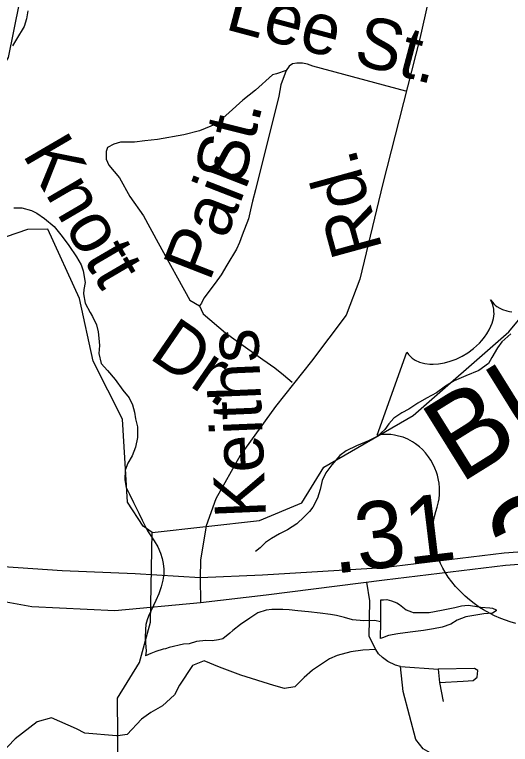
# Model space of a CAD drawing. Extents: x 2001466 to 31450019, y -30647475 to 847247.
# Drawn here: x 2164743 to 2166590, y 747443 to 750161 of the extents above; entities that cross this region are included whole.
import ezdxf

# ---------------------------------------------------------------- set-up
doc = ezdxf.new("R2010")
doc.units = 0
for name, color, linetype in [('Exist Hydrographic Creek Single Shore', 7, 'Continuous'), ('Exist Hydrographic Misc Water Feature', 7, 'Continuous'), ('Exist Road Non-System Type 51', 7, 'Continuous'), ('Exist Road Non-System Type 51 Label', 7, 'Continuous'), ('Exist Road Primary US Divided Attributed', 7, 'Continuous'), ('Exist Road Primary US Mileage Hundredths English Label', 7, 'Continuous'), ('Exist Road Primary US Shield CELL', 7, 'Continuous'), ('Exist Road Primary US Shield Number Label', 7, 'Continuous'), ('Exist Road Secondary Type 51 Attributed', 7, 'Continuous'), ('Exist Road Secondary Type 51 Label', 7, 'Continuous')]:
    doc.layers.add(name, color=color, linetype=linetype)

msp = doc.modelspace()

# ---------------------------------------------------------------- linework, layer by layer
at = {"layer": 'Exist Hydrographic Creek Single Shore'}
for points in [[(2165255.1, 748232.2), (2165222, 748255.9), (2165163.2, 748345.7), (2165145.2, 748654.4), (2165035.2, 748869.9), (2164984.2, 749103.9), (2164866.1, 749362.2), (2164791.2, 749360.4), (2164591.1, 749292.4), (2164549.1, 749335.9), (2164564.2, 749752.2), (2164720.1, 750001.6), (2164761.1, 750204.1), (2164758.2, 750686.4), (2164716.2, 750861.2), (2164615.1, 750994.4), (2164540.2, 751051.7), (2164539.2, 751166.6), (2164580.2, 751218.2), (2164572.2, 751300.4), (2164471.1, 751443.5), (2164568.1, 751933.6), (2164482.2, 752407.8), (2164448.2, 752467.5)], [(2165126.8, 747475), (2165126.1, 747614.9), (2165208.1, 747747.7), (2165249.1, 747897.8), (2165255.1, 748232.2)], [(2165559.1, 745607.9), (2165536.2, 745641.5), (2165510.1, 745907.8), (2165583.1, 746185), (2165583.1, 746309.8), (2165515.1, 746458.7), (2165440.2, 746565.3), (2165380.1, 746865), (2165262.2, 746972.4), (2165127.1, 747414.7), (2165126.8, 747475)]]:
    msp.add_lwpolyline(points, dxfattribs=at)
at = {"layer": 'Exist Hydrographic Misc Water Feature'}
for points in [[(2165255.1, 748232.2), (2165655.1, 748276.5), (2165813.2, 748342.2), (2165895.2, 748475), (2166227.2, 748668.3), (2166584.2, 748979.2), (2166766.1, 749198.6), (2166790.1, 749306.3), (2166906.1, 749540.2), (2167163.1, 749708.7), (2167353.2, 749934.5), (2167469.2, 750210.9), (2167476.2, 750351.9), (2167409.1, 750418.8), (2167392.1, 750501.2), (2167458.1, 750624.5), (2167607.2, 750785.4), (2167681, 750918.5), (2167678.2, 751420.4), (2167708.1, 751961.1), (2167839.1, 752493.1), (2167953.1, 752851.6)], [(2164791.6, 750175.6), (2164787.5, 750145.4), (2164777.7, 750117.6), (2164749.8, 750069.6), (2164734.2, 750045.1)], [(2164739.6, 749441.5), (2164769.3, 749441.9), (2164805.6, 749431.9), (2164825.5, 749422), (2164853.6, 749402), (2164889.9, 749372.5), (2164919.8, 749334.4), (2164944.2, 749300.7), (2164972.7, 749259), (2164990.5, 749229.1), (2164998.7, 749207.2), (2165005.1, 749163.3), (2165001.2, 749137.1), (2164999.4, 749121.1), (2165005.1, 749087), (2165023.6, 749051.4), (2165033.4, 749037.3), (2165048.2, 749005.4), (2165053.9, 748979.4), (2165056.4, 748955.5), (2165058.4, 748929.3), (2165056.4, 748899.5), (2165064.6, 748861.4), (2165088.8, 748835.8), (2165117.1, 748801.9), (2165145.4, 748762), (2165169.6, 748733.9), (2165181.4, 748708.2), (2165189.4, 748680.2), (2165193.5, 748656.1), (2165200.1, 748626.3), (2165200.1, 748586.5), (2165192.5, 748550.4), (2165180.6, 748518.1), (2165164.6, 748490.1), (2165155.2, 748463.9), (2165152.9, 748428.2), (2165158.9, 748400.1), (2165171.2, 748374.3), (2165185.3, 748344.2), (2165205.4, 748304.6), (2165217.7, 748278.4), (2165237.8, 748238.5), (2165262.6, 748200.7), (2165276.4, 748179.1), (2165286.8, 748154.8), (2165292.4, 748134.9), (2165296.7, 748117.2), (2165298.9, 748095), (2165298.7, 748081.2)], [(2166591.2, 748972.1), (2166557.8, 748941.9), (2166542.2, 748919.9), (2166520.4, 748883.8), (2166508.1, 748861.7), (2166472.5, 748835.5), (2166424.5, 748815.2), (2166380.6, 748797), (2166348.8, 748776.7), (2166315, 748752.7), (2166276.8, 748732.5), (2166245.3, 748714.1), (2166211.4, 748692.1), (2166185.2, 748677.8), (2166155.4, 748657.9), (2166137.6, 748637.5), (2166121.6, 748615.5), (2166093.9, 748589.3), (2166061.9, 748573.1), (2166016, 748554.9), (2165978.1, 748536.6), (2165954.3, 748518.7), (2165924.4, 748484.3), (2165902.8, 748454.4), (2165888.9, 748426.4), (2165880.9, 748392.3), (2165871, 748360.2), (2165853.4, 748325.9), (2165841.3, 748309.9), (2165821.4, 748290.2), (2165793.7, 748264), (2165759.9, 748241.5), (2165729.8, 748227.4), (2165700, 748209.2), (2165678.1, 748195), (2165658.2, 748175.3), (2165640.1, 748161)], [(2165298.7, 748081.2), (2165298.9, 748077.1), (2165294.8, 748055), (2165289.3, 748029.1), (2165279.5, 748003), (2165269.4, 747978.9), (2165241.9, 747920.7), (2165236.2, 747906.9), (2165231.9, 747888.9), (2165230.2, 747870.9), (2165228.6, 747840.7), (2165230.5, 747820.9), (2165232.5, 747790.6), (2165230.9, 747772.6)], [(2166107.5, 747899.7), (2166107.1, 747981.7), (2166117.3, 747981.8), (2166129.2, 747982), (2166146.8, 747978.1), (2166167.1, 747970.2), (2166177.4, 747964.2), (2166189.7, 747954.2), (2166201.6, 747944.3), (2166221.5, 747936.4), (2166227.6, 747934.3), (2166287.1, 747934.6), (2166333.6, 747943), (2166383.3, 747953.3), (2166407.2, 747959.4), (2166433.1, 747961.6), (2166457.1, 747957.6), (2166479.4, 747953.8), (2166513.5, 747951.9), (2166523.3, 747950), (2166537.3, 747944.2), (2166537.5, 747940.1), (2166523.3, 747932.1), (2166491.1, 747929.7), (2166461.2, 747923.7), (2166423.7, 747917.6), (2166391.9, 747905.4), (2166367.9, 747891.2), (2166335.7, 747879), (2166304.1, 747872.8), (2166266, 747866.8), (2166216.1, 747860.2), (2166170, 747854.1), (2166135.8, 747848), (2166114, 747839.9), (2166106, 747837.8), (2166107.5, 747899.7)], [(2166107.5, 747899.7), (2166083.5, 747903.7), (2166043.5, 747903.3), (2166001.7, 747907.2), (2165971.9, 747914.9), (2165941.8, 747922.7), (2165919.4, 747926.5), (2165881.7, 747932.2), (2165837.6, 747936), (2165797.6, 747940.1), (2165765.4, 747943.7), (2165741.6, 747945.7), (2165701.5, 747945.3), (2165679.5, 747943.3), (2165649.4, 747933.3), (2165619.6, 747913), (2165583.8, 747888.8), (2165556.3, 747866.6), (2165544, 747856.7), (2165518.1, 747836.3), (2165502.6, 747832.2), (2165478.6, 747828.1), (2165454.6, 747830.1), (2165420.3, 747825.9), (2165392.7, 747817.6), (2165372.4, 747815.7), (2165318.4, 747803.2), (2165304.5, 747799.2), (2165296.5, 747797.2), (2165268.4, 747788.9), (2165250.5, 747781), (2165230.9, 747772.6)]]:
    msp.add_lwpolyline(points, dxfattribs=at)
at = {"layer": 'Exist Road Non-System Type 51'}
for p, q in [((2166066.3, 747978), (2166055.6, 748047.1)), ((2166180.8, 747732.9), (2166321.1, 747723.1)), ((2166321.1, 747723.1), (2166326, 747673.8)), ((2166326, 747673.8), (2166339.4, 747602.7))]:
    msp.add_line(p, q, dxfattribs=at)
for points in [[(2166201, 749876.6), (2165853.9, 749968.9), (2165833.7, 749976.7), (2165815.8, 749980.5), (2165793.8, 749980.3), (2165777.7, 749978), (2165765.8, 749969.9), (2165754, 749953.7)], [(2165754, 749953.7), (2165718.3, 749941.3), (2165703.5, 749936.4), (2165639.8, 749880), (2165593.3, 749843.2), (2165541.8, 749796.6), (2165495.2, 749754.9), (2165431.5, 749727.9), (2165372.7, 749713.2), (2165274.7, 749696.1), (2165228.1, 749691.1), (2165188.9, 749686.2), (2165137.4, 749686.2), (2165112.9, 749678.9), (2165088.4, 749666.6), (2165083.5, 749651.9), (2165083.5, 749634.7), (2165083.5, 749622.5), (2165093.3, 749600.4), (2165133, 749553.4), (2165171.4, 749484.3), (2165223.2, 749411.6), (2165277.1, 749311), (2165395.1, 749098), (2165431.3, 749076.4)], [(2165754, 749953.7), (2165734.5, 749899.5), (2165727.1, 749857.5), (2165640.7, 749508.7), (2165629.3, 749466.5), (2165621.6, 749434.5), (2165613.9, 749400.3), (2165590.5, 749340.2), (2165580.9, 749311.9), (2165569, 749287.8), (2165533.8, 749227.5), (2165512, 749191.4), (2165490.4, 749161), (2165447.1, 749104.5), (2165439.3, 749086.5), (2165431.3, 749076.4)], [(2165431.3, 749076.4), (2165437.4, 749062.5), (2165445.7, 749046.5), (2165528.4, 748975.5), (2165568.6, 748947.8), (2165667.6, 748877), (2165711.9, 748845.5), (2165744.2, 748819.9), (2165776.4, 748792.2)], [(2166088.7, 747796.3), (2166064.3, 747845.2), (2166066.3, 747978)], [(2166088.7, 747796.3), (2166039.8, 747794.2), (2165995, 747788.1), (2165944, 747773.8), (2165915.5, 747761.6), (2165852.3, 747718.8), (2165821.7, 747692.3), (2165787, 747656.6), (2165748.4, 747651.5), (2165708.2, 747661.6), (2165585.1, 747701), (2165506.3, 747730.5), (2165448.4, 747753.4), (2165405.6, 747737.1), (2165356.6, 747663.7), (2165338.3, 747627), (2165293.5, 747586.2), (2165250.7, 747561.7), (2165216, 747537.3), (2165161.7, 747479.3), (2165126.8, 747475)], [(2166180.8, 747732.9), (2166162.1, 747737.3), (2166133.6, 747751.6), (2166113.2, 747765.9), (2166098.9, 747780.2), (2166088.7, 747796.3)], [(2166404.7, 747202.2), (2166407.2, 747251.5), (2166397.4, 747308.1), (2166365.4, 747352.4), (2166308.7, 747401.7), (2166264.4, 747426.3), (2166237.4, 747460.8), (2166190.6, 747639.3), (2166180.8, 747732.9)], [(2166326, 747673.8), (2166414.6, 747678.7), (2166451.5, 747681.2), (2166466.3, 747693.5), (2166468.7, 747718.1), (2166456.4, 747725.5), (2166321.1, 747723.1)], [(2165126.8, 747475), (2165122.3, 747474.4), (2165004.1, 747484.2), (2164973.5, 747500.6), (2164879.7, 747541.3), (2164826.8, 747527.1), (2164745.2, 747463.8), (2164688.2, 747404.7), (2164643.3, 747327.2), (2164616.8, 747243.6), (2164584.2, 747162)]]:
    msp.add_lwpolyline(points, dxfattribs=at)
at = {"layer": 'Exist Road Primary US Divided Attributed'}
for points in [[(2165434.6, 748063.1), (2165192.4, 748077.8), (2164920.4, 748089.3), (2164590.7, 748111.3), (2164336.7, 748133.8), (2163873, 748329.8), (2163408.5, 748539.2), (2162316.3, 749007.1)], [(2162302.1, 748964.1), (2163390.4, 748498.1), (2163855, 748288.6), (2164311.4, 748076.7), (2164545.7, 748003.4), (2164806.3, 747956.3), (2165116, 747941.7), (2165435, 747971.3)], [(2167092, 748171.9), (2166821.9, 748173.6), (2166567.3, 748154.6), (2166116.1, 748100.1), (2165666.4, 748072.6), (2165434.6, 748063.1)], [(2165435, 747971.3), (2165680, 747999.3), (2166120.9, 748055.4), (2166571.6, 748109.9), (2166823.4, 748128.6), (2167091.1, 748127)]]:
    msp.add_lwpolyline(points, dxfattribs=at)
at = {"layer": 'Exist Road Primary US Shield CELL'}
msp.add_lwpolyline([(2166609.8, 747892.5), (2166589, 747898.7), (2166554.5, 747911.5), (2166531.1, 747921.8), (2166514.9, 747930.1), (2166490.2, 747944), (2166475.5, 747953.3), (2166455.2, 747967.5), (2166437.7, 747981.1), (2166421.8, 747994.5), (2166412.2, 748003.4), (2166396.5, 748019.6), (2166385.7, 748031.3), (2166371.9, 748047.9), (2166358.6, 748066.3), (2166347.3, 748083.8), (2166338.6, 748098.8), (2166329.6, 748117), (2166321.2, 748137), (2166314.9, 748154.8), (2166311.1, 748168), (2166307.2, 748184.5), (2166303.9, 748203.5), (2166302.2, 748222.4), (2166301.6, 748238.7), (2166302.2, 748257), (2166303.9, 748273.2), (2166307.5, 748292.3), (2166312.2, 748310.6), (2166317.4, 748325.9), (2166322.3, 748346.2), (2166324.3, 748357.7), (2166325.7, 748373.1), (2166326, 748386.7), (2166325.6, 748398.5), (2166324.3, 748415.4), (2166322.3, 748427.4), (2166318.2, 748445.3), (2166314.3, 748457.2), (2166308.6, 748472.1), (2166302.5, 748485.6), (2166293.4, 748501.6), (2166285, 748514.3), (2166273.9, 748528.3), (2166262.1, 748541), (2166250.8, 748551.5), (2166236.4, 748562.6), (2166224.8, 748570.1), (2166207.5, 748579.2), (2166190, 748586.7), (2166173.6, 748591.5), (2166157.9, 748595.2), (2166144.1, 748596.6), (2166131.4, 748597.5), (2166116.1, 748597.3), (2166102.1, 748595.9), (2166093.7, 748594.4), (2166203.7, 748904.3), (2166209.9, 748895.6), (2166218.7, 748886.3), (2166223.8, 748881.8), (2166235.5, 748874.3), (2166251.5, 748866.9), (2166270.7, 748861.9), (2166290.4, 748859.3), (2166302.7, 748859.1), (2166322.5, 748860.3), (2166343.9, 748863.8), (2166366.1, 748870.1), (2166387.7, 748878.2), (2166410.1, 748888.9), (2166431.1, 748901.5), (2166452.5, 748917.1), (2166474.3, 748937.3), (2166483.9, 748947.4), (2166494, 748959.8), (2166502.8, 748972.1), (2166511.5, 748987.1), (2166517.7, 749000.3), (2166522.2, 749011.4), (2166526.9, 749029.7), (2166529, 749046.9), (2166528.8, 749055.8), (2166528.3, 749064.1), (2166524.7, 749080.1), (2166522.4, 749086.7), (2166515.8, 749099.3), (2166522.8, 749089.7), (2166527.8, 749084), (2166533.3, 749078.8), (2166540, 749073.9), (2166550.4, 749067.5), (2166560.4, 749062.9), (2166577.3, 749057.5), (2166586.9, 749055.6), (2166595.3, 749054.6)], dxfattribs=at)
at = {"layer": 'Exist Road Secondary Type 51 Attributed'}
for points in [[(2166470.9, 753794.2), (2166462.5, 753507.3), (2166447.9, 753207.8), (2166419.6, 752583.7), (2166402.9, 752187.9), (2166398.7, 751894.7), (2166374.6, 751329.2), (2166351.6, 750812), (2166327.5, 750543.9), (2166315, 750349.1), (2166252.2, 750072.7), (2166115.1, 749532.4), (2166029.3, 749176.4), (2165978, 749042.3), (2165848.3, 748870.6), (2165714.4, 748701), (2165582.5, 748518.8), (2165492.5, 748357.5), (2165455.9, 748257), (2165435, 748129.2), (2165434.6, 748063.1)], [(2165434.6, 748063.1), (2165435, 747971.3)]]:
    msp.add_lwpolyline(points, dxfattribs=at)

# ---------------------------------------------------------------- texts
at = {"layer": 'Exist Road Non-System Type 51 Label'}
for s, rotation, p in [('Lee St.', 345.1065, (2165522, 750108.1)), ('St.', 76.0957, (2165593.4, 749522.5)), ('Knott', 300.2958, (2164769.7, 749641.1)), ('Pair', 68.7066, (2165468.7, 749163.1)), ('Dr.', 325.5246, (2165238.7, 748884.2))]:
    msp.add_text(s, height=190, rotation=rotation, dxfattribs=at).set_placement(p)
at = {"layer": 'Exist Road Primary US Mileage Hundredths English Label'}
msp.add_text('.31', height=250, rotation=6.8842, dxfattribs=at).set_placement((2165933.2, 748078.1))
at = {"layer": 'Exist Road Primary US Shield Number Label'}
for s, height, p in [('BUS', 310, (2166401.4, 748411.7)), ('264', 360, (2166655.8, 747969.6))]:
    msp.add_text(s, height=height, rotation=31.918, dxfattribs=at).set_placement(p)
at = {"layer": 'Exist Road Secondary Type 51 Label'}
for s, rotation, p in [('Rd.', 105.3565, (2166114.7, 749288.4)), ('Keiths', 92.4276, (2165679.7, 748289.5))]:
    msp.add_text(s, height=190, rotation=rotation, dxfattribs=at).set_placement(p)

doc.saveas('drawing.dxf')
